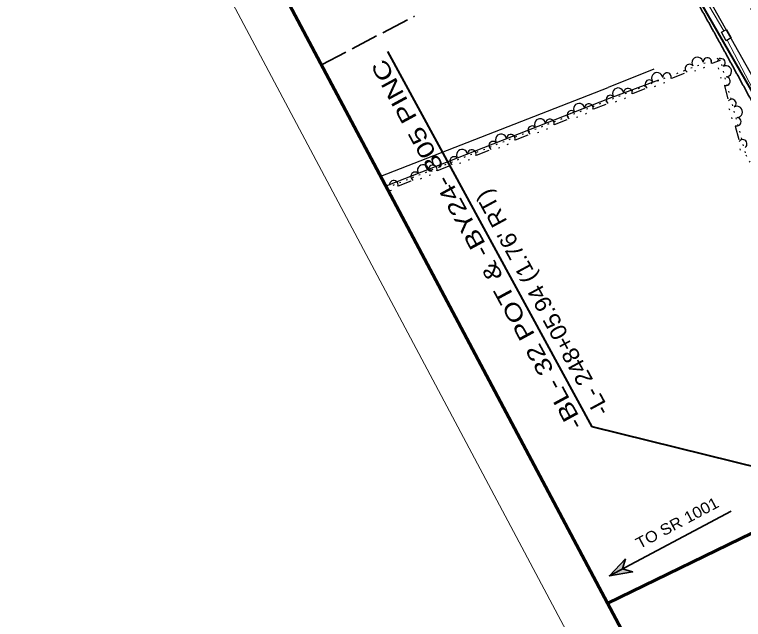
# Model space of a CAD drawing. Extents: x 2402199 to 2404507, y 568050 to 571478.
# Drawn here: x 2402199.5 to 2402420.4, y 570929.4 to 571112.8 of the extents above; entities that cross this region are included whole.
import ezdxf
from ezdxf.enums import TextEntityAlignment as Align

# ---------------------------------------------------------------- set-up
doc = ezdxf.new("R2010")
doc.units = 0
doc.header["$LTSCALE"] = 1.4
for name, pattern in [('DOTTED', [1.5, 0.3, -1.2]), ('LONG_DASHED', [7.5, 6, -1.5]), ('MEDIUM_DASHED', [4.5, 3, -1.5])]:
    doc.linetypes.add(name, pattern=pattern)
for name, color, linetype, lineweight in [('1', 7, 'Continuous', 35), ('10', 7, 'Continuous', 25), ('11', 7, 'Continuous', 25), ('15', 7, 'DOTTED', 40), ('17', 7, 'MEDIUM_DASHED', 35), ('21', 7, 'Continuous', 40), ('27', 7, 'Continuous', 80), ('28', 7, 'Continuous', 25), ('3', 7, 'Continuous', 25), ('6', 7, 'Continuous', 35), ('62', 7, 'Continuous', 60), ('63', 7, 'Continuous', 35)]:
    doc.layers.add(name, color=color, linetype=linetype, lineweight=lineweight)
doc.layers.add('23', color=7, linetype='Continuous')

msp = doc.modelspace()

# ---------------------------------------------------------------- hatches: boundary and pattern name
at = {"layer": '10'}
msp.add_hatch(color=256, dxfattribs=at).paths.add_polyline_path([(2402384.646, 570947.815), (2402379.743, 570942.659), (2402386.759, 570943.841), (2402383.716, 570944.771)])

# ---------------------------------------------------------------- linework, layer by layer
at = {"layer": '1'}
for points in [[(2402414.666, 571101.586), (2402414.237, 571102.366), (2402413.803, 571103.154), (2402413.373, 571103.933), (2402412.944, 571104.713), (2402412.514, 571105.491), (2402412.084, 571106.271), (2402411.654, 571107.049), (2402411.223, 571107.828), (2402410.792, 571108.606), (2402410.361, 571109.385), (2402409.93, 571110.163), (2402409.498, 571110.941), (2402409.061, 571111.727), (2402408.629, 571112.505), (2402408.197, 571113.283), (2402407.765, 571114.06), (2402407.332, 571114.838), (2402406.899, 571115.615), (2402406.466, 571116.392), (2402406.032, 571117.169), (2402405.598, 571117.946), (2402405.165, 571118.723), (2402404.73, 571119.499), (2402404.296, 571120.276), (2402403.856, 571121.061), (2402403.422, 571121.837), (2402402.986, 571122.613), (2402402.551, 571123.39), (2402402.115, 571124.165), (2402401.68, 571124.941), (2402401.243, 571125.716), (2402400.806, 571126.492), (2402400.37, 571127.267), (2402399.933, 571128.042), (2402399.496, 571128.817), (2402399.053, 571129.601), (2402398.616, 571130.375), (2402398.178, 571131.15), (2402397.74, 571131.924), (2402397.302, 571132.699), (2402396.863, 571133.473), (2402396.424, 571134.247), (2402395.985, 571135.021), (2402395.546, 571135.795), (2402395.106, 571136.569), (2402394.666, 571137.342), (2402394.221, 571138.124), (2402393.781, 571138.897), (2402393.34, 571139.671), (2402392.9, 571140.443), (2402392.459, 571141.216), (2402392.018, 571141.989), (2402391.576, 571142.761), (2402391.134, 571143.534), (2402390.692, 571144.306), (2402390.25, 571145.079), (2402389.808, 571145.851), (2402389.36, 571146.631), (2402388.916, 571147.403), (2402388.474, 571148.174), (2402388.03, 571148.946), (2402387.586, 571149.718), (2402387.143, 571150.489), (2402386.698, 571151.26), (2402386.254, 571152.031), (2402385.809, 571152.802), (2402385.365, 571153.572), (2402384.919, 571154.343), (2402384.469, 571155.122), (2402384.023, 571155.892), (2402383.577, 571156.662), (2402383.131, 571157.432), (2402382.238, 571158.973)], [(2402445.746, 571043.492), (2402445.335, 571044.281), (2402444.925, 571045.069), (2402444.513, 571045.858), (2402444.102, 571046.647), (2402443.691, 571047.436), (2402443.279, 571048.224), (2402442.867, 571049.012), (2402442.454, 571049.8), (2402442.041, 571050.588), (2402441.624, 571051.385), (2402441.211, 571052.172), (2402440.797, 571052.96), (2402440.384, 571053.748), (2402439.97, 571054.535), (2402439.556, 571055.322), (2402439.142, 571056.109), (2402438.727, 571056.897), (2402438.312, 571057.684), (2402437.897, 571058.47), (2402437.482, 571059.257), (2402437.062, 571060.052), (2402436.646, 571060.838), (2402436.23, 571061.624), (2402435.813, 571062.41), (2402435.397, 571063.196), (2402434.98, 571063.983), (2402434.563, 571064.768), (2402434.146, 571065.554), (2402433.728, 571066.339), (2402433.311, 571067.125), (2402432.893, 571067.91), (2402432.47, 571068.703), (2402432.051, 571069.488), (2402431.632, 571070.273), (2402431.213, 571071.058), (2402430.794, 571071.843), (2402430.374, 571072.627), (2402429.954, 571073.411), (2402429.535, 571074.196), (2402429.114, 571074.98), (2402428.694, 571075.764), (2402428.273, 571076.547), (2402427.848, 571077.34), (2402427.426, 571078.123), (2402427.005, 571078.906), (2402426.583, 571079.69), (2402426.161, 571080.473), (2402425.739, 571081.256), (2402425.316, 571082.039), (2402424.894, 571082.822), (2402424.471, 571083.604), (2402424.047, 571084.387), (2402423.624, 571085.169), (2402423.195, 571085.96), (2402422.771, 571086.742), (2402422.347, 571087.524), (2402421.923, 571088.306), (2402421.498, 571089.088), (2402421.073, 571089.87), (2402420.648, 571090.651), (2402420.223, 571091.432), (2402419.797, 571092.214), (2402419.371, 571092.995), (2402418.945, 571093.775), (2402418.514, 571094.565), (2402418.087, 571095.346), (2402417.66, 571096.126), (2402417.233, 571096.907), (2402416.806, 571097.687), (2402416.378, 571098.467), (2402415.95, 571099.247), (2402415.522, 571100.027), (2402415.094, 571100.807), (2402414.665, 571101.587)]]:
    msp.add_spline(points, degree=3, dxfattribs=at)
at = {"layer": '10'}
for p, q in [((2402393.21, 571096.219), (2402379.347, 571090.663)), ((2402394.572, 571092.879), (2402379.688, 571087.325)), ((2402310.424, 571063.757), (2402379.347, 571090.663)), ((2402379.688, 571087.325), (2402312.006, 571060.782))]:
    msp.add_line(p, q, dxfattribs=at)
at = {"layer": '10', "lineweight": 35}
msp.add_lwpolyline([(2402384.646, 570947.815), (2402379.743, 570942.659), (2402386.759, 570943.841), (2402383.716, 570944.771)], close=True, dxfattribs=at)
at = {"layer": '11'}
for p, q in [((2402410.854, 571098.033), (2402413.407, 571098.953)), ((2402405.592, 571095.701), (2402405.977, 571095.839)), ((2402408.293, 571096.674), (2402408.679, 571096.814)), ((2402412.685, 571096.633), (2402412.791, 571096.236)), ((2402398.632, 571093.489), (2402402.447, 571094.993)), ((2402413.429, 571093.862), (2402413.535, 571093.466)), ((2402396.113, 571092.056), (2402396.494, 571092.206)), ((2402386.803, 571088.829), (2402390.619, 571090.333)), ((2402393.441, 571091.003), (2402393.823, 571091.154)), ((2402414.569, 571091.194), (2402415.633, 571087.234)), ((2402384.282, 571087.395), (2402384.663, 571087.544)), ((2402374.975, 571084.169), (2402378.791, 571085.672)), ((2402381.61, 571086.342), (2402381.992, 571086.492)), ((2402372.454, 571082.734), (2402372.835, 571082.884)), ((2402415.981, 571084.354), (2402416.088, 571083.958)), ((2402363.147, 571079.508), (2402366.962, 571081.012)), ((2402369.782, 571081.682), (2402370.164, 571081.832)), ((2402416.725, 571081.581), (2402416.832, 571081.184)), ((2402360.626, 571078.074), (2402361.007, 571078.224)), ((2402417.865, 571078.916), (2402418.928, 571074.955)), ((2402351.319, 571074.848), (2402355.134, 571076.351)), ((2402357.953, 571077.021), (2402358.336, 571077.171)), ((2402339.49, 571070.187), (2402343.306, 571071.691)), ((2402346.127, 571072.361), (2402346.508, 571072.511)), ((2402348.797, 571073.413), (2402349.179, 571073.563)), ((2402419.277, 571072.078), (2402419.383, 571071.682)), ((2402334.299, 571067.701), (2402334.68, 571067.851)), ((2402336.969, 571068.753), (2402337.351, 571068.903)), ((2402327.662, 571065.527), (2402331.478, 571067.03)), ((2402322.473, 571063.04), (2402322.854, 571063.191)), ((2402325.141, 571064.092), (2402325.522, 571064.243)), ((2402315.834, 571060.866), (2402319.649, 571062.369)), ((2402313.315, 571059.432), (2402313.697, 571059.583))]:
    msp.add_line(p, q, dxfattribs=at)
at = {"layer": '11', "linetype": 'DOTTED'}
msp.add_line((2402312.245, 571060.333), (2402402.474, 571095.885), dxfattribs=at)
msp.add_lwpolyline([(2402402.474, 571095.885), (2402413.129, 571099.725), (2402421.048, 571070.224), (2402472.559, 570975.083)], dxfattribs=at)
at = {"layer": '11'}
for centre, radius, start, end in [((2402406.44, 571098.186), 1.691, 5.78059, 213.85308), ((2402409.419, 571098.388), 1.297, 340.58532, 181.38189), ((2402413.554, 571098.14), 1.297, 303.46121, 144.25778), ((2402404.017, 571096.441), 1.297, 38.25179, 239.04836), ((2402415.09, 571095.58), 1.691, 270.99002, 119.06251), ((2402394.214, 571093.512), 1.691, 7.46916, 215.54165), ((2402397.186, 571093.801), 1.297, 342.27389, 183.07046), ((2402415.043, 571092.595), 1.297, 245.79474, 86.59131), ((2402391.844, 571091.697), 1.297, 39.94036, 240.73693), ((2402382.386, 571088.852), 1.691, 7.46916, 215.54165), ((2402385.358, 571089.141), 1.297, 342.27389, 183.07046), ((2402380.016, 571087.036), 1.297, 39.94036, 240.73693), ((2402416.85, 571085.862), 1.297, 303.46121, 144.25778), ((2402370.558, 571084.191), 1.691, 7.46916, 215.54165), ((2402373.529, 571084.48), 1.297, 342.27389, 183.07046), ((2402418.387, 571083.302), 1.691, 270.99002, 119.06251), ((2402368.188, 571082.376), 1.297, 39.94036, 240.73693), ((2402358.73, 571079.531), 1.691, 7.46916, 215.54165), ((2402361.701, 571079.82), 1.297, 342.27389, 183.07046), ((2402418.339, 571080.317), 1.297, 245.79474, 86.59131), ((2402356.36, 571077.715), 1.297, 39.94036, 240.73693), ((2402346.902, 571074.87), 1.691, 7.46916, 215.54165), ((2402349.873, 571075.159), 1.297, 342.27389, 183.07046), ((2402344.531, 571073.055), 1.297, 39.94036, 240.73693), ((2402420.146, 571073.583), 1.297, 303.46121, 144.25778), ((2402335.073, 571070.21), 1.691, 7.46916, 215.54165), ((2402338.045, 571070.499), 1.297, 342.27389, 183.07046), ((2402332.703, 571068.394), 1.297, 39.94036, 240.73693), ((2402323.245, 571065.549), 1.691, 7.46916, 215.54165), ((2402326.217, 571065.838), 1.297, 342.27389, 183.07046), ((2402320.875, 571063.734), 1.297, 39.94036, 240.73693), ((2402314.389, 571061.178), 1.297, 342.27389, 183.07046)]:
    msp.add_arc(centre, radius, start, end, dxfattribs=at)
at = {"layer": '15'}
msp.add_arc((2399911.332, 569690.208), 2887.133, 22.84472, 37.57762, dxfattribs=at)
at = {"layer": '17', "linetype": 'LONG_DASHED'}
msp.add_line((2402292.456, 571097.55), (2402320.706, 571112.334), dxfattribs=at)
at = {"layer": '21'}
msp.add_line((2402453.011, 570968.339), (2402374.495, 570987.785), dxfattribs=at)
msp.add_lwpolyline([(2402571.932, 570780.533), (2402538.299, 570859.007), (2402503.143, 570934.851), (2402464.804, 571011.777), (2402426.113, 571084.024), (2402384.214, 571156.832), (2402372.534, 571175.865)], dxfattribs=at)
at = {"layer": '27', "lineweight": 35}
msp.add_line((2402379.743, 570942.659), (2402416.665, 570962.291), dxfattribs=at)
at = {"layer": '28'}
msp.add_lwpolyline([(2402374.812, 571177.076), (2402399.705, 571135.603), (2402440.232, 571063.522), (2402479.967, 570987.625), (2402515.512, 570914.776), (2402552.113, 570833.795), (2402574.37, 570781.072)], dxfattribs=at)
at = {"layer": '3', "lineweight": 40}
msp.add_lwpolyline([(2402571.932, 570780.533), (2402538.299, 570859.007), (2402503.143, 570934.851), (2402464.804, 571011.777), (2402426.113, 571084.024), (2402384.214, 571156.832), (2402372.534, 571175.865)], dxfattribs=at)
at = {"layer": '3'}
msp.add_lwpolyline([(2402374.812, 571177.076), (2402399.705, 571135.603), (2402440.232, 571063.522), (2402479.967, 570987.625), (2402515.512, 570914.776), (2402552.113, 570833.795), (2402574.37, 570781.072)], dxfattribs=at)
at = {"layer": '6', "lineweight": 13}
for p, q in [((2402373.595, 571177.375), (2402414.387, 571107.848)), ((2402415.453, 571105.055), (2402511.71, 570919.872))]:
    msp.add_line(p, q, dxfattribs=at)
at = {"layer": '6', "lineweight": 25}
msp.add_lwpolyline([(2402415.226, 571108.265), (2402416.632, 571105.705), (2402415.093, 571104.86), (2402413.688, 571107.42)], close=True, dxfattribs=at)
at = {"layer": '62'}
msp.add_line((2402379.217, 570934.377), (2402649.132, 571065.756), dxfattribs=at)
msp.add_arc((2399929.798, 569697.989), 2887.133, 22.84477, 31.13893, dxfattribs=at)
at = {"layer": '63', "lineweight": 13}
msp.add_line((2402247.375, 571150.383), (2402486.806, 570700.08), dxfattribs=at)
at = {"layer": '63', "lineweight": 60}
msp.add_line((2402492.519, 570721.286), (2402266.253, 571146.83), dxfattribs=at)
at = {"layer": '63', "lineweight": 40}
msp.add_line((2402374.495, 570987.785), (2402312.546, 571101.626), dxfattribs=at)

# ---------------------------------------------------------------- texts
at = {"layer": '1'}
for s, width, p in [('-BL- 32 POT & -BY24- 305 PINC', 1.3, (2402372.036, 570988.502)), ("-L- 248+05.94 (1.76' RT)", 1.05, (2402379.948, 570992.792))]:
    msp.add_text(s, height=5, rotation=118.473, dxfattribs=dict(at, width=width)).set_placement(p)
at = {"layer": '23', "width": 1.1}
msp.add_text('TO SR 1001', height=3.375, rotation=28, dxfattribs=at).set_placement((2402401.062, 570957.185), align=Align.CENTER)

doc.saveas('drawing.dxf')
